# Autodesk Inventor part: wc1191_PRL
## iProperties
Shininess: 64.0
Length Units: 11272
Angle Units: 11279
Time Units: 11290
Mass Units: 11286
Length Display Precision: 3
Angle Display Precision: 2
Compacted: True
Part Number: wc1191_PRL
Document SubType Name: Modeling
Created: 2004-08
Designer: John Blackburn
Manufacturer: Standard
Standards Organization: Custom
Material: Phenolic
Density: 0.0
Volumn: 0.0
Area: 0.0
PropertySet Name: Model Information
Control State: 0
Master: False
Checked Out: False
Author: John Blackburn
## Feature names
1. Revolution1
